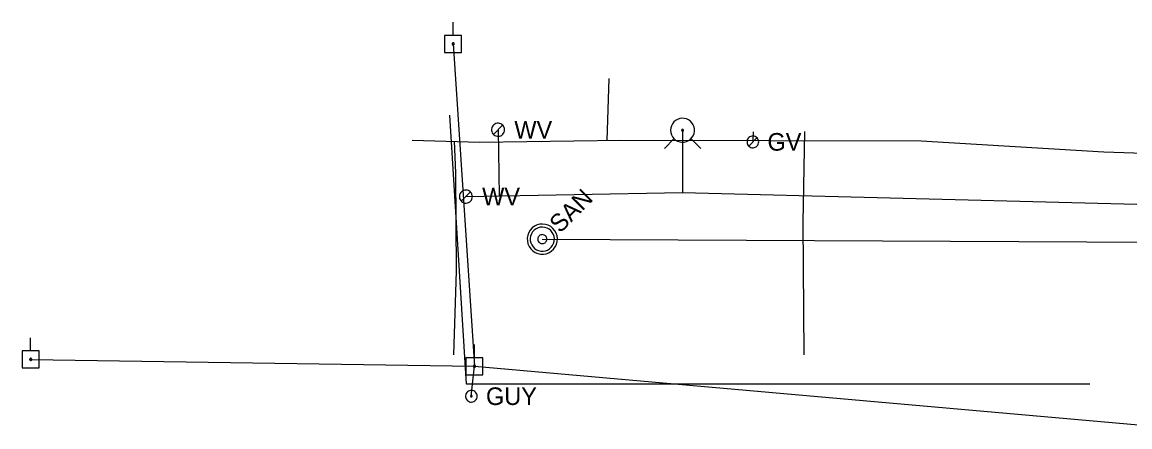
# Model space of a CAD drawing. Extents: x 596028 to 606371, y 330010 to 403088.
# Drawn here: x 604362.7 to 604605.3, y 331376.9 to 331465.4 of the extents above; entities that cross this region are included whole.
import ezdxf

# ---------------------------------------------------------------- set-up
doc = ezdxf.new("R2010")
doc.units = 0
for name, color, linetype in [('E_UTL_EGuyWire', 7, 'Continuous'), ('E_UTL_EPowerPole', 7, 'Continuous'), ('E_UTL_FO_UG', 7, 'Continuous'), ('E_UTL_G', 7, 'Continuous'), ('E_UTL_G_UG', 7, 'Continuous'), ('E_UTL_Overhead', 7, 'Continuous'), ('E_UTL_SAN_MH', 7, 'Continuous'), ('E_UTL_SAN_UG', 7, 'Continuous'), ('E_UTL_W', 7, 'Continuous'), ('E_UTL_W_UG', 7, 'Continuous'), ('E_UTL_WHydrant', 7, 'Continuous')]:
    doc.layers.add(name, color=color, linetype=linetype)

msp = doc.modelspace()

# ---------------------------------------------------------------- linework, layer by layer
at = {"layer": 'E_UTL_EGuyWire'}
msp.add_line((604461.11, 331383.58), (604461.8, 331390.13), dxfattribs=at)
for points in [[(604462.39, 331383.58), (604462.37, 331383.82), (604462.3, 331384.06), (604462.19, 331384.28), (604462.04, 331384.47), (604461.85, 331384.63), (604461.64, 331384.75), (604461.41, 331384.83), (604461.17, 331384.86), (604460.93, 331384.85), (604460.69, 331384.79), (604460.47, 331384.69), (604460.27, 331384.55), (604460.1, 331384.37), (604459.97, 331384.17), (604459.88, 331383.94), (604459.83, 331383.7), (604459.83, 331383.46), (604459.88, 331383.22), (604459.97, 331382.99), (604460.1, 331382.79), (604460.27, 331382.61), (604460.47, 331382.47), (604460.69, 331382.37), (604460.93, 331382.31), (604461.17, 331382.3), (604461.41, 331382.33), (604461.64, 331382.41), (604461.85, 331382.54), (604462.04, 331382.7), (604462.19, 331382.89), (604462.3, 331383.1), (604462.37, 331383.34), (604462.39, 331383.58)], [(604461.27, 331383.58), (604461.27, 331383.61), (604461.26, 331383.64), (604461.25, 331383.67), (604461.23, 331383.69), (604461.2, 331383.71), (604461.18, 331383.73), (604461.15, 331383.74), (604461.12, 331383.74), (604461.09, 331383.74), (604461.06, 331383.73), (604461.03, 331383.72), (604461.01, 331383.7), (604460.98, 331383.68), (604460.97, 331383.65), (604460.96, 331383.63), (604460.95, 331383.6), (604460.95, 331383.57), (604460.96, 331383.54), (604460.97, 331383.51), (604460.98, 331383.48), (604461.01, 331383.46), (604461.03, 331383.44), (604461.06, 331383.43), (604461.09, 331383.42), (604461.12, 331383.42), (604461.15, 331383.43), (604461.18, 331383.44), (604461.2, 331383.45), (604461.23, 331383.47), (604461.25, 331383.49), (604461.26, 331383.52), (604461.27, 331383.55), (604461.27, 331383.58)]]:
    msp.add_lwpolyline(points, dxfattribs=at)
at = {"layer": 'E_UTL_EPowerPole'}
for points in [[(604457.12, 331462.48), (604457.12, 331465.39)], [(604458.96, 331462.48), (604455.27, 331462.48)], [(604455.27, 331462.48), (604455.27, 331458.79)], [(604458.96, 331458.79), (604458.96, 331462.48)], [(604457.39, 331460.64), (604457.38, 331460.69), (604457.37, 331460.73), (604457.35, 331460.77), (604457.32, 331460.8), (604457.29, 331460.83), (604457.25, 331460.86), (604457.21, 331460.87), (604457.16, 331460.88), (604457.12, 331460.88), (604457.07, 331460.87), (604457.03, 331460.85), (604456.99, 331460.82), (604456.96, 331460.79), (604456.94, 331460.75), (604456.92, 331460.71), (604456.91, 331460.66), (604456.91, 331460.62), (604456.92, 331460.57), (604456.94, 331460.53), (604456.96, 331460.49), (604456.99, 331460.46), (604457.03, 331460.43), (604457.07, 331460.41), (604457.12, 331460.4), (604457.16, 331460.4), (604457.21, 331460.41), (604457.25, 331460.42), (604457.29, 331460.45), (604457.32, 331460.48), (604457.35, 331460.51), (604457.37, 331460.55), (604457.38, 331460.59), (604457.39, 331460.64)], [(604455.27, 331458.79), (604458.96, 331458.79)], [(604364.59, 331393.47), (604364.59, 331396.38)], [(604461.77, 331391.97), (604461.77, 331394.88)], [(604366.44, 331393.47), (604362.75, 331393.47)], [(604362.75, 331393.47), (604362.75, 331389.78)], [(604364.86, 331391.63), (604364.86, 331391.68), (604364.85, 331391.72), (604364.83, 331391.76), (604364.8, 331391.8), (604364.76, 331391.83), (604364.72, 331391.85), (604364.68, 331391.86), (604364.64, 331391.87), (604364.59, 331391.87), (604364.55, 331391.86), (604364.51, 331391.84), (604364.47, 331391.81), (604364.44, 331391.78), (604364.41, 331391.74), (604364.4, 331391.7), (604364.39, 331391.65), (604364.39, 331391.61), (604364.4, 331391.56), (604364.41, 331391.52), (604364.44, 331391.48), (604364.47, 331391.45), (604364.51, 331391.43), (604364.55, 331391.41), (604364.59, 331391.4), (604364.64, 331391.39), (604364.68, 331391.4), (604364.72, 331391.42), (604364.76, 331391.44), (604364.8, 331391.47), (604364.83, 331391.5), (604364.85, 331391.54), (604364.86, 331391.59), (604364.86, 331391.63)], [(604366.44, 331389.78), (604366.44, 331393.47)], [(604463.61, 331391.97), (604459.92, 331391.97)], [(604459.92, 331391.97), (604459.92, 331388.28)], [(604463.61, 331388.28), (604463.61, 331391.97)], [(604362.75, 331389.78), (604366.44, 331389.78)], [(604462.04, 331390.13), (604462.03, 331390.18), (604462.02, 331390.22), (604462, 331390.26), (604461.97, 331390.29), (604461.94, 331390.32), (604461.9, 331390.35), (604461.86, 331390.36), (604461.81, 331390.37), (604461.77, 331390.37), (604461.72, 331390.36), (604461.68, 331390.34), (604461.64, 331390.31), (604461.61, 331390.28), (604461.59, 331390.24), (604461.57, 331390.2), (604461.56, 331390.15), (604461.56, 331390.11), (604461.57, 331390.06), (604461.59, 331390.02), (604461.61, 331389.98), (604461.64, 331389.95), (604461.68, 331389.92), (604461.72, 331389.9), (604461.77, 331389.89), (604461.81, 331389.89), (604461.86, 331389.9), (604461.9, 331389.91), (604461.94, 331389.94), (604461.97, 331389.97), (604462, 331390), (604462.02, 331390.04), (604462.03, 331390.08), (604462.04, 331390.13)], [(604459.92, 331388.28), (604463.61, 331388.28)]]:
    msp.add_lwpolyline(points, dxfattribs=at)
at = {"layer": 'E_UTL_FO_UG'}
msp.add_lwpolyline([(604596.56, 331386.24), (604460.07, 331386.24), (604456.42, 331445.07)], dxfattribs=at)
at = {"layer": 'E_UTL_G'}
for points in [[(604524.04, 331439.21), (604524.01, 331439.45), (604523.94, 331439.69), (604523.83, 331439.9), (604523.68, 331440.1), (604523.5, 331440.26), (604523.29, 331440.38), (604523.06, 331440.46), (604522.81, 331440.49), (604522.57, 331440.48), (604522.33, 331440.42), (604522.11, 331440.32), (604521.91, 331440.18), (604521.74, 331440), (604521.61, 331439.8), (604521.52, 331439.57), (604521.48, 331439.33), (604521.48, 331439.09), (604521.52, 331438.85), (604521.61, 331438.62), (604521.74, 331438.42), (604521.91, 331438.24), (604522.11, 331438.1), (604522.33, 331438), (604522.57, 331437.94), (604522.81, 331437.93), (604523.06, 331437.96), (604523.29, 331438.04), (604523.5, 331438.16), (604523.68, 331438.32), (604523.83, 331438.52), (604523.94, 331438.73), (604524.01, 331438.97), (604524.04, 331439.21)], [(604521.85, 331438.3), (604523.66, 331440.12)]]:
    msp.add_lwpolyline(points, dxfattribs=at)
at = {"layer": 'E_UTL_G_UG'}
for points in [[(604491.2, 331453.07), (604490.75, 331439.53)], [(604522.85, 331441.44), (604522.75, 331439.21)], [(604534.02, 331392.62), (604533.81, 331421.54), (604534.15, 331441.46)], [(604448.13, 331439.59), (604462.99, 331439.17)], [(604457.3, 331392.64), (604457.84, 331410.91), (604457.74, 331432.43), (604457.42, 331439.33)], [(604462.99, 331439.17), (604493.85, 331439.57), (604559.63, 331439.45), (604599.63, 331437), (604654.59, 331435.18), (604688.27, 331435.25)]]:
    msp.add_lwpolyline(points, dxfattribs=at)
at = {"layer": 'E_UTL_Overhead'}
for points in [[(604457.15, 331460.64), (604461.8, 331390.13)], [(604364.63, 331391.63), (604461.8, 331390.13), (604612.18, 331376.89)]]:
    msp.add_lwpolyline(points, dxfattribs=at)
at = {"layer": 'E_UTL_SAN_MH'}
for points in [[(604478.99, 331420.27), (604478.5, 331420.67), (604477.95, 331420.97), (604477.35, 331421.16), (604476.73, 331421.23), (604476.11, 331421.19), (604475.5, 331421.03), (604474.94, 331420.75), (604474.43, 331420.38), (604474.01, 331419.91), (604473.68, 331419.38), (604473.47, 331418.79), (604473.36, 331418.17), (604473.38, 331417.54), (604473.51, 331416.93), (604473.76, 331416.35), (604474.11, 331415.83), (604474.55, 331415.39), (604475.07, 331415.04), (604475.65, 331414.79), (604476.26, 331414.66), (604476.89, 331414.64), (604477.51, 331414.75), (604478.09, 331414.97), (604478.63, 331415.29), (604479.09, 331415.71), (604479.47, 331416.22), (604479.74, 331416.78), (604479.91, 331417.39), (604479.95, 331418.01), (604479.88, 331418.64), (604479.69, 331419.23), (604479.39, 331419.78), (604478.99, 331420.27)], [(604478.52, 331419.8), (604478.13, 331420.12), (604477.69, 331420.36), (604477.21, 331420.51), (604476.72, 331420.57), (604476.21, 331420.54), (604475.73, 331420.41), (604475.28, 331420.19), (604474.88, 331419.89), (604474.54, 331419.52), (604474.28, 331419.09), (604474.1, 331418.62), (604474.02, 331418.12), (604474.03, 331417.62), (604474.14, 331417.13), (604474.34, 331416.67), (604474.62, 331416.25), (604474.97, 331415.9), (604475.39, 331415.62), (604475.85, 331415.42), (604476.34, 331415.31), (604476.84, 331415.3), (604477.34, 331415.38), (604477.81, 331415.56), (604478.23, 331415.82), (604478.61, 331416.16), (604478.91, 331416.56), (604479.13, 331417.01), (604479.26, 331417.5), (604479.29, 331418), (604479.23, 331418.5), (604479.08, 331418.97), (604478.84, 331419.41), (604478.52, 331419.8)], [(604477.35, 331418.63), (604477.21, 331418.75), (604477.04, 331418.84), (604476.86, 331418.9), (604476.68, 331418.92), (604476.49, 331418.91), (604476.31, 331418.86), (604476.14, 331418.78), (604475.99, 331418.67), (604475.86, 331418.53), (604475.76, 331418.37), (604475.7, 331418.19), (604475.67, 331418.01), (604475.67, 331417.82), (604475.71, 331417.63), (604475.78, 331417.46), (604475.89, 331417.3), (604476.02, 331417.17), (604476.18, 331417.07), (604476.35, 331416.99), (604476.54, 331416.95), (604476.72, 331416.95), (604476.91, 331416.98), (604477.09, 331417.04), (604477.25, 331417.14), (604477.39, 331417.27), (604477.5, 331417.42), (604477.58, 331417.59), (604477.63, 331417.77), (604477.64, 331417.96), (604477.62, 331418.15), (604477.56, 331418.32), (604477.47, 331418.49), (604477.35, 331418.63)]]:
    msp.add_lwpolyline(points, dxfattribs=at)
at = {"layer": 'E_UTL_SAN_UG'}
msp.add_line((604476.65, 331417.91), (604676.22, 331417.01), dxfattribs=at)
at = {"layer": 'E_UTL_W'}
for points in [[(604468.39, 331441.86), (604468.36, 331442.13), (604468.29, 331442.39), (604468.16, 331442.63), (604468, 331442.85), (604467.79, 331443.02), (604467.56, 331443.16), (604467.3, 331443.25), (604467.03, 331443.29), (604466.76, 331443.27), (604466.5, 331443.21), (604466.25, 331443.1), (604466.03, 331442.94), (604465.84, 331442.74), (604465.7, 331442.51), (604465.6, 331442.26), (604465.54, 331442), (604465.54, 331441.73), (604465.6, 331441.46), (604465.7, 331441.21), (604465.84, 331440.98), (604466.03, 331440.78), (604466.25, 331440.63), (604466.5, 331440.51), (604466.76, 331440.45), (604467.03, 331440.44), (604467.3, 331440.48), (604467.56, 331440.56), (604467.79, 331440.7), (604468, 331440.88), (604468.16, 331441.09), (604468.29, 331441.33), (604468.36, 331441.59), (604468.39, 331441.86)], [(604465.95, 331440.85), (604467.97, 331442.87)], [(604461.35, 331427.24), (604461.32, 331427.51), (604461.24, 331427.77), (604461.12, 331428.01), (604460.95, 331428.23), (604460.75, 331428.4), (604460.51, 331428.54), (604460.26, 331428.63), (604459.99, 331428.67), (604459.72, 331428.65), (604459.45, 331428.59), (604459.21, 331428.48), (604458.99, 331428.32), (604458.8, 331428.12), (604458.65, 331427.9), (604458.55, 331427.64), (604458.5, 331427.38), (604458.5, 331427.11), (604458.55, 331426.84), (604458.65, 331426.59), (604458.8, 331426.36), (604458.99, 331426.16), (604459.21, 331426.01), (604459.45, 331425.89), (604459.72, 331425.83), (604459.99, 331425.82), (604460.26, 331425.86), (604460.51, 331425.95), (604460.75, 331426.08), (604460.95, 331426.26), (604461.12, 331426.47), (604461.24, 331426.71), (604461.32, 331426.97), (604461.35, 331427.24)], [(604458.91, 331426.23), (604460.93, 331428.25)]]:
    msp.add_lwpolyline(points, dxfattribs=at)
at = {"layer": 'E_UTL_W_UG'}
for points in [[(604466.96, 331441.86), (604467.24, 331427.38)], [(604507.36, 331441.76), (604507.36, 331428.16)], [(604459.92, 331427.24), (604507.36, 331428.16), (604734.76, 331422.27), (604734.76, 331422.27)]]:
    msp.add_lwpolyline(points, dxfattribs=at)
at = {"layer": 'E_UTL_WHydrant'}
for points in [[(604504.74, 331441.76), (604504.79, 331441.26), (604504.93, 331440.78), (604505.16, 331440.34), (604505.47, 331439.95), (604505.84, 331439.62), (604506.27, 331439.37), (604506.75, 331439.21), (604507.24, 331439.14), (604507.74, 331439.16), (604508.22, 331439.28), (604508.68, 331439.49), (604509.08, 331439.77), (604509.43, 331440.14), (604509.7, 331440.56), (604509.88, 331441.02), (604509.98, 331441.51), (604509.98, 331442.01), (604509.88, 331442.5), (604509.7, 331442.96), (604509.43, 331443.38), (604509.08, 331443.74), (604508.68, 331444.03), (604508.22, 331444.24), (604507.74, 331444.35), (604507.24, 331444.38), (604506.75, 331444.31), (604506.27, 331444.14), (604505.84, 331443.89), (604505.47, 331443.57), (604505.16, 331443.17), (604504.93, 331442.73), (604504.79, 331442.25), (604504.74, 331441.76)], [(604505.53, 331439.92), (604503.39, 331437.78)], [(604507.16, 331441.76), (604507.17, 331441.72), (604507.18, 331441.68), (604507.2, 331441.65), (604507.22, 331441.62), (604507.25, 331441.59), (604507.28, 331441.57), (604507.32, 331441.56), (604507.35, 331441.56), (604507.39, 331441.56), (604507.43, 331441.57), (604507.46, 331441.58), (604507.5, 331441.61), (604507.52, 331441.63), (604507.54, 331441.66), (604507.56, 331441.7), (604507.56, 331441.74), (604507.56, 331441.78), (604507.56, 331441.81), (604507.54, 331441.85), (604507.52, 331441.88), (604507.5, 331441.91), (604507.46, 331441.93), (604507.43, 331441.95), (604507.39, 331441.96), (604507.35, 331441.96), (604507.32, 331441.95), (604507.28, 331441.94), (604507.25, 331441.92), (604507.22, 331441.9), (604507.2, 331441.87), (604507.18, 331441.83), (604507.17, 331441.79), (604507.16, 331441.76)], [(604509.2, 331439.92), (604511.34, 331437.78)]]:
    msp.add_lwpolyline(points, dxfattribs=at)

# ---------------------------------------------------------------- texts
at = {"layer": 'E_UTL_EGuyWire'}
msp.add_text('GUY', height=3.85, dxfattribs=at).set_placement((604464.32, 331381.66))
at = {"layer": 'E_UTL_G'}
msp.add_text('GV', height=3.85, dxfattribs=at).set_placement((604525.96, 331437.29))
at = {"layer": 'E_UTL_SAN_MH'}
msp.add_text('SAN', height=3.849, rotation=45, dxfattribs=at).set_placement((604480.55, 331419.08))
at = {"layer": 'E_UTL_W'}
for p in [(604470.53, 331439.94), (604463.48, 331425.32)]:
    msp.add_text('WV', height=3.85, dxfattribs=at).set_placement(p)

doc.saveas('drawing.dxf')
